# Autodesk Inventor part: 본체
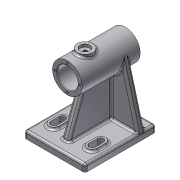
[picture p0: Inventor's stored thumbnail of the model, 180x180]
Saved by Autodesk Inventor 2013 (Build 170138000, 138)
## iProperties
Created: 2019-10
Part Number: 본체
Material: 알루미늄 6061
Document SubType Name: Modeling
Designer: default
Density: 2.71 g/cm^3
Sheet Metal Rule: 기본값
Mass: 590.147 g
Surface Area: 539.917 cm^2
Volume: 217.766 cm^3
Author: default
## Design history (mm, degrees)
sketch "스케치1"
  geometry: L1 (-43, -50)-(43, -50); L2 (43, -50)-(43, 50); L3 (43, 50)-(-43, 50); L4 (-43, 50)-(-43, -50); L5 (-43, -50)-(43, 50); L6 (43, -50)-(-43, 50); 1 further point
  constraints: 12 end point, 2 midpoint, 2 parallel, 1 horizontal, 1 perpendicular
  dimensions: "d0" = 100 distance between parallel lines of L1 L3; "d2" = 86 distance between parallel lines of L4 L2
extrude "돌출1" new body sketch "스케치1" distance "d3" = 10; taper "d4" = 0 deg
sketch "스케치2"
  geometry: L1 (-43, -50)-(43, -50) reference; L2 (43, -50)-(43, 50) reference; L3 (-34, -24)-(-34, -12); L4 (-20, -24)-(-20, -12); L5 (0, 0)-(0, -50); L6 (34, -24)-(34, -12); L7 (20, -24)-(20, -12); A1 r 7 centre (-27, -24) between (-34, -24) and (-20, -24); A2 r 7 centre (-27, -12) between (-20, -12) and (-34, -12); A3 r 7 centre (27, -24) between (20, -24) and (34, -24); A4 r 7 centre (27, -12) between (34, -12) and (20, -12)
  constraints: 10 end point, 8 point on circle, 6 symmetric about line, 4 centre point, 4 tangent, 2 parallel, 1 midpoint, 2 other
  dimensions: "d5" = 14 distance between parallel lines of L4 L3; "d7" = 27 horizontal distance of L5.start A1.centre; "d8" = 26 distance from line of L1 A1.centre; "d9" = 12 distance of A2.centre A1.centre
extrude "돌출2" join sketch "스케치2" distance "d10" = 3; taper "d11" = 0 deg
sketch "스케치3"
  geometry: L1 (-20, -24)-(-20, -12) reference; L2 (0, 0)-(0, -55.2); L3 (-31.5, -12)-(-31.5, -24); L4 (-22.5, -12)-(-22.5, -24); L5 (22.5, -12)-(22.5, -24); L6 (31.5, -12)-(31.5, -24); A1 r 7 centre (-27, -24) between (-34, -24) and (-20, -24) reference; A2 r 7 centre (-27, -12) between (-20, -12) and (-34, -12) reference; A3 r 4.5 centre (-27, -12) between (-22.5, -12) and (-31.5, -12); A4 r 4.5 centre (-27, -24) between (-31.5, -24) and (-22.5, -24); A5 r 4.5 centre (27, -24) between (22.5, -24) and (31.5, -24); A6 r 4.5 centre (27, -12) between (31.5, -12) and (22.5, -12)
  constraints: 10 end point, 8 point on circle, 6 symmetric about line, 4 centre point, 3 parallel, 2 coincident, 2 tangent, 2 other
  dimensions: "d12" = 9 diameter of A3; "d14" = 9 diameter of A4
extrude "돌출3" cut sketch "스케치3" stored distance "d15" = 3; taper "d16" = 0 deg
sketch "스케치4"
  geometry: L1 (86, 32)-(86, -50); L2 (0, 50)-(0, -50) reference; L3 (107, 32)-(100.5, 32); L4 (100.5, 32)-(100.5, -27.696); L5 (100.5, -27.696)-(97.5, -27.696); L6 (97.5, -27.696)-(97.5, -50); L7 (97.5, -50)-(107, -50); L8 (107, -50)-(107, 32); L9 (0, -50)-(10, -50) reference; 1 further point
  constraints: 14 end point, 4 parallel, 2 perpendicular, 2 point on line, 1 collinear, 1 vertical
  dimensions: "d17" = 86 distance between parallel lines of L2 L1; "d18" = 82 distance between parallel lines of L7 L3; "d19" = 23 diameter of L6 L1; "d20" = 42 diameter of L8 L1; "d21" = 29 diameter of L4 L1
revolve "회전1" sketch "스케치4" stored, may be unused: angle "d22" = 90 deg
node "작업 평면1"
fillet "모깎기1" dims "d24" = 3
sketch "스케치7"
  geometry: L1 (22.728, 91.48)-(0.104, 7.783); L2 (63.272, 91.48)-(85.896, 7.783); L3 (3, 10)-(83, 10); A1 r 21 centre (43, 86) between (22.728, 91.48) and (63.272, 91.48) reference; A2 r 3 centre (3, 7) between (3, 10) and (0, 7) reference; A3 r 3 centre (83, 7) between (86, 7) and (83, 10) reference; A4 r 3 centre (3, 7) between (3, 10) and (0.104, 7.783); A5 r 21 centre (43, 86) between (22.728, 91.48) and (63.272, 91.48); A6 r 3 centre (83, 7) between (85.896, 7.783) and (83, 10); 1 further point
  constraints: 8 point on circle, 8 tangent, 6 end point, 3 centre point, 3 concentric, 1 horizontal
extrude "돌출4" join sketch "스케치7" distance "d26" = 10; taper "d27" = 0 deg
sketch "스케치8"
  geometry: L1 (10, 35)-(69, 13.526); L2 (0, 50)-(7, 50) reference; L3 (10, 47)-(10, -25) reference; L4 (10, 35)-(10, -25); L5 (10, -25)-(69, -25); L6 (69, -25)-(69, 13.526); 1 further point
  constraints: 8 end point, 2 perpendicular, 1 collinear, 1 point on line
  dimensions: "d28" = 15 distance from line of L2 L1.start; "d29" = 70 deg angle of L3 L1; "d30" = 59 distance between parallel lines of L6 L3
extrude "돌출5" join sketch "스케치8" stored distance "d31" = 10; taper "d32" = 0 deg
fillet "모깎기3" dims "d34" = 3
node "작업 평면2"
sketch "스케치9"
  geometry: L1 (0, 0)-(0, 32.696); L2 (-21, 32)-(21, 32) reference; C1 r 11 at (0, 7)
  constraints: 2 end point, 1 centre point, 1 point on line, 1 vertical
  dimensions: "d36" = 22 diameter of C1; "d38" = 25 distance from line of L2 C1.centre
extrude "돌출6" join sketch "스케치9" stored distance "d39" = 10; taper "d40" = 0 deg
fillet "모깎기4" dims "d41" = 3
sketch "스케치10" dims "d5" = 14, "d7" = 27, "d8" = 26, "d9" = 12
  geometry: A1 r 11 centre (0, -7) between (0, 4) and (0, -18) reference; 2 further points
  constraints: 1 coincident
hole "구멍1" sketch "스케치10" at (0, -7) diameter "d42" = 4.917; stored, may be unused: countersink angle "d46" = 90 deg, drill point angle "d48" = 118 deg; dims "d43" = 14, "d44" = 14, "d45" = 4, "d47" = 15
chamfer "모따기1" distance "d49" = 1; stored, may be unused: second distance "d50" = 2, angle "d51" = 45 deg
sketch "스케치16" dims "d55" = 36
  geometry: L1 (0, 0)-(0, 18); C1 r 15.5 at (0, 0) reference; 2 further points
  constraints: 2 coincident, 2 end point, 1 vertical, 1 vertical alignment, 2 other
hole "구멍2" sketch "스케치16" at (0, 18) diameter "d57" = 2.459; stored, may be unused: countersink angle "d61" = 90 deg, drill point angle "d63" = 118 deg; dims "d58" = 8, "d59" = 14, "d60" = 4, "d62" = 10
node "작업 평면3"
sketch "스케치17"
  geometry: L1 (40, 50)-(-40, 50) reference; L2 (43, -47)-(43, 47) reference; 2 further points
  constraints: 1 other
  dimensions: "d67" = 7 distance from line of L1 point (0, 43); "d68" = 43 distance from line of L2 point (0, 43)
feature "엠보싱1" sketch "스케치17" dims "d0" = 100, "d2" = 86, "d5" = 14, "d7" = 27, "d8" = 26, "d9" = 12, "d69" = 0.5, "d70" = 0
node "솔리드1"
pattern_circular "원형 패턴1" dims angle "d65" = 360 deg
mirror "대칭1"
other parameters: "d23" = -75
